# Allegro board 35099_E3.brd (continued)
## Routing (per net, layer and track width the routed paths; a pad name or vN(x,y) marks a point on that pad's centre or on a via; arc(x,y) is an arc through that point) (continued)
N19546803: length 3.1
  TOP w0.114: U108.A2 R249.2
N19546823: length 2.5
  TOP w0.114: U108.A5 79.53,55.32 R250.2
N19546843: length 2
  TOP w0.114: R251.2 U108.B1
N19546881: length 3.4
  TOP w0.114: R247.2 82.53,48.33 82.03,48.82 82.03,50.82 U108.C2
N19798378: length 1.7
  TOP w0.114: J38.6 SH17.1
N19798386: length 1.7
  TOP w0.114: J38.38 SH21.1
N19798394: length 2.1
  TOP w0.114: SH20.1 63.44,105.57 J38.28
N19798402: length 1.7
  TOP w0.114: J38.26 SH19.1
N19798410: length 2
  TOP w0.114: J38.24 63.38,106.84 SH18.1
N19799787: length 2.1
  TOP w0.114: SH11.2 72.51,111.28 J38.9
N19799813: length 1.7
  TOP w0.114: SH12.2 J38.11
N19799835: length 1.7
  TOP w0.114: J38.15 SH13.2
N19799857: length 2.1
  TOP w0.114: SH14.2 72.45,108.74 J38.17
N19830189: length 3.1
  TOP w0.114: R363.2 U19.A2
N19830205: length 2.4
  TOP w0.114: U19.B1 62.54,49.32 R365.1
N19830207: length 1.5
  TOP w0.114: R365.2 TP45.1
N19830220: length 5.1
  TOP w0.114: U19.A3 63.04,51.82 63.54,51.82 64.04,51.32 64.04,48.82 R364.1
N19830414: length 2
  TOP w0.114: R362.2 U19.A5
N19896770: length 3.6
  TOP w0.114: J45.9 61.08,39.33 R201.2
N19896842: length 3.4
  TOP w0.114: J45.11 61.58,39.79 R202.2
N19896868: length 3.2
  TOP w0.114: R203.2 62.08,40.24 J45.13
N19896897: length 3
  TOP w0.114: J45.15 62.58,40.69 R204.2
N19896926: length 2.8
  TOP w0.114: R205.2 63.08,41.13 J45.17
N19896944: length 3
  TOP w0.114: R206.2 63.58,40.68 J45.19
N19896964: length 3.2
  TOP w0.114: J45.21 64.08,40.22 R207.2
N19896972: length 3.4
  TOP w0.114: J45.23 64.58,39.77 R208.2
N19896981: length 93
  TOP w0.114: v1(136.78,28.96) 148.26,28.96 D23.C ; J45.6 60.33,29.46 62.61,27.18 76.96,27.18 v1(77.98,28.19)
  L3_IN1 w0.114: v1(136.78,28.96) 135.71,27.89 86.78,27.89 86.21,28.45 78.23,28.45 v1(77.98,28.19)
N19897044: length 91.4
  TOP w0.114: v1(136.27,23.37) 148.17,23.37 D22.C ; v1(77.09,28.19) 76.45,27.56 64.91,27.56 62.83,29.64 J45.16
  L3_IN1 w0.114: v1(136.27,23.37) 134.62,25.02 80.26,25.02 v1(77.09,28.19)
N19897050: length 1.2
  TOP w0.114: R225.1 D23.A
N19897088: length 2.9
  TOP w0.114: J45.20 v1(63.83,32.44)
  BOTTOM w0.114: R209.2 63.72,32.54 v1(63.83,32.44)
N19897150: length 1.2
  TOP w0.114: D22.A R224.1
N19897259: length 3.1
  TOP w0.114: J45.8 v1(60.83,32.44)
  BOTTOM w0.114: R215.1 60.83,32.54 v1(60.83,32.44)
N19897289: length 2.9
  TOP w0.114: J45.10 v1(61.33,31.93)
  BOTTOM w0.114: v1(61.33,31.93) 61.33,32.99 R216.1
N19897307: length 2.7
  TOP w0.114: J45.12 v1(61.83,32.44)
  BOTTOM w0.114: R217.1 61.81,32.45 v1(61.83,32.44)
N19897327: length 2.9
  TOP w0.114: J45.14 v1(62.33,31.93)
  BOTTOM w0.114: v1(62.33,31.93) 62.33,33.01 R218.1
N19898667: length 1.5
  TOP w0.114: Y8.3 R200.1
N20219970: length 2.2
  TOP w0.114: TP46.1 R393.3
N169660511: length 1.7
  TOP w0.254: C15.2 34.8,102.11 R27.1
N169660621: length 1
  TOP w0.203: C17.2 R38.1

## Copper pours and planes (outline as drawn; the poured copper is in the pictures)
2V5_OUT on TOP: 112.8,74.64 111.8,75.64 111.8,77.42 111.94,77.56 113.11,77.56 113.11,76.2 122.59,76.2 122.97,75.82 122.97,74.75 122.86,74.64
3V3_OUT on TOP: 105.31,35.18 105.31,36.5 108,36.5 110.16,38.66 115.84,38.66 116.09,38.41 116.09,37.43 116,37.34 110.62,37.34 108.46,35.18
3V3_OUT_USB1 on TOP: 102.02,50.37 99.98,48.33 99.98,46.68 101.38,46.68 101.38,47.58 102.67,48.87 103.42,48.87 103.61,49.06 103.61,50.37
+2.5V_LINK on L3_IN1: 111.63,79.38 111.63,86.42 98.55,99.5 98.55,105 100.27,106.72 118.48,106.72 129.98,118.23 132.21,118.23 135.38,115.05 135.38,111.56 133.48,109.66 131.57,109.66 131.57,108.41 133.77,108.41 134.11,108.07 134.11,102.99 130.13,99.01 125.37,99.01 121.73,95.37 121.73,89.65 121.73,89.65 121.73,88.07 112.52,78.86 112.15,78.86
+5V on TOP: 103.44,48.39 102.59,48.39 102.59,47.12 102.06,46.58 102.06,37.99 102.34,37.71 102.34,37.01 103.2,37.01 103.2,37.62 103.34,37.76 105.12,37.76 105.27,37.6 105.27,37.01 106.15,37.01 106.15,38.29 105.77,38.67 104.33,38.67 104.11,38.89 104.11,45.51 105.15,46.55 106.82,46.55 108.58,48.31 108.58,53.34 108.2,53.72 106.55,53.72 105.51,52.68 105.51,49.86 106.48,49.86 106.63,49.71 106.63,48.49 106.5,48.36 105.56,48.36 105.56,47.9 105.27,47.61 103.5,47.61 103.44,47.68
+5V on TOP: 141.74,73.19 144.78,73.19 144.78,77.61 141.88,77.61 141.3,77.04 141.3,73.63
+5V_EXT on TOP: 139.5,65.76 138.51,66.75 138.51,73.86 138.15,74.22 137.19,74.22 136.53,74.88 136.53,77.62 136.58,77.67 136.75,77.67 136.78,77.65 136.78,77.39 136.93,77.25 137.05,77.25 137.13,77.16 137.13,76.83 137.62,76.35 138.66,76.35 140.97,74.04 140.97,68.76 141.53,68.2 146.53,68.2 147.24,67.49 149.11,67.49 149.12,67.48 149.12,67.14 148.18,67.14 147.9,66.87 147.9,66.74 147.9,66.73 147.9,66.38 147.28,65.76
+5V_LINK on TOP: 145.24,74.22 147.75,74.22 148.08,74.55 148.08,75.31 147.83,75.56 145.29,75.56 145.03,75.31 145.03,74.42
+5V_LINK on TOP: 122.96,73.4 118.36,73.4 118.17,73.2 118.17,70.81 118.71,70.27 121.48,70.27 122.96,71.75
+5V_LINK on TOP: 143.66,106.43 141.43,106.43 141.12,106.12 141.12,105.05 141.42,104.76 143.52,104.76 143.81,105.04 143.81,105.04 143.81,106.27
+5V_LINK on L3_IN1: 120.02,70.74 119.25,71.5 119.25,72.14 121.28,74.17 134.8,74.17 141.48,80.85 141.48,105.66 142.11,106.3 143.38,106.3 144.15,105.54 144.15,78.99 148.08,75.06 148.08,74.55 147.7,74.17 139.33,74.17 135.9,70.74
GND on TOP (solid shape): 145.91,109.46 145.91,109.31 145.91,109.28 145.9,109.21 145.83,109.17 145.76,109.14 145.69,109.09 145.59,109 143.43,109 143.43,109.09 143.46,109.11 143.55,109.18 143.59,109.28 143.59,109.84 145.53,109.84
GND on TOP (solid shape): 105.15,113.56 105.19,113.51 105.21,113.47 105.18,113.43 105,113.25 104.93,113 104.93,112.93 104.71,112.71 96.11,112.71 96.02,112.77 96.04,112.88 96.71,113.56
GND on TOP (solid shape): 102.23,70.15 101.79,69.71 101.29,69.71 101.22,69.74 101.19,69.82 101.19,70.03 101.16,70.12 101.07,70.15 101.04,70.15 101.02,70.14 100.94,70.26 100.84,70.35 100.8,70.42 100.83,70.5 101.43,71.1 102.23,71.1
GND on TOP (solid shape): 102.23,68.33 102.23,67.54 98.64,67.54 98.55,67.61 98.57,67.72 98.73,67.88 99.52,67.88 99.69,67.73 99.91,67.68 100.21,67.78 100.38,68.05 100.42,68.11 100.49,68.13 100.56,68.12 100.83,68.2 101.02,68.41 101.04,68.4 101.07,68.4 101.16,68.44 101.19,68.53 101.19,68.74 101.22,68.82 101.29,68.85 101.71,68.85
GND on TOP (solid shape): 33.82,101.35 34.12,101.05 34.23,100.98 34.35,100.95 38.06,100.95 38.15,100.9 38.15,100.81 38.11,100.7 38.1,100.58 38.18,100.31 38.39,100.13 38.38,100.1 38.38,100.08 38.42,99.99 38.51,99.95 38.71,99.95 38.8,99.99 38.84,100.08 38.83,100.1 38.83,100.13 38.92,100.18 38.99,100.25 39.24,100.25 39.32,100.18 39.41,100.13 39.4,100.1 39.4,100.08 39.4,100.05 39.41,100.03 39.19,99.84 39.12,99.57 39.12,99.53 38.92,99.33 37.61,99.33 36.3,100.64 36.19,100.71 36.07,100.74 34.22,100.74 33.65,101.3 33.71,101.35
GND on TOP (solid shape): 112.95,105.96 113.12,105.82 113.33,105.77 113.43,105.77 113.52,105.8 113.61,105.79 113.66,105.71 113.66,104.41 113.38,104.13 113.28,104.14 113.01,104.06 112.83,103.85 112.71,103.84 112.65,103.73 112.65,103.53 112.71,103.42 112.83,103.41 113.01,103.2 113.28,103.12 113.38,103.13 113.56,102.95 113.51,102.9 112.06,102.9 111.95,102.87 111.86,102.81 109.19,100.15 109.08,100.13 109.02,100.22 109.02,100.97 111.38,103.33 111.44,103.42 111.46,103.53 111.46,105.42 112.01,105.96
GND on TOP (solid shape): 47.18,82.5 47.24,82.5 48.17,82.5 48.32,82.39 48.5,82.34 48.52,82.34 48.59,82.27 48.59,82.26 48.68,82.01 48.89,81.85 48.92,81.84 48.92,79.42 48.34,78.84 48.11,78.84 48.01,78.92 47.9,78.97 47.83,79.05 47.86,79.14 47.91,79.21 47.96,79.28 47.98,79.28 48.01,79.27 48.1,79.31 48.13,79.4 48.13,79.6 48.1,79.69 48.02,79.73 47.98,79.74 47.98,80.35 47.84,80.69 47.5,80.84 47.27,80.78 47.1,80.62 47.06,80.6 47.02,80.61 46.98,80.65 46.98,81.22 46.99,81.23 47.01,81.29 47.02,81.34 47.02,82.26 47.01,82.31 46.99,82.36 46.99,82.47 47.07,82.52 47.11,82.52
GND on TOP (solid shape): 116.3,105.57 116.32,105.47 116.24,105.4 116.02,105.31 115.87,105.12 115.85,105.13 115.82,105.13 115.73,105.09 115.7,105 115.7,104.8 115.7,104.77 115.68,104.69 115.61,104.65 115.28,104.5 115.15,104.17 115.18,103.99 115.28,103.84 115.28,103.83 115.3,103.69 115.38,103.58 115.42,103.53 115.43,103.48 115.39,103.45 114.95,103.45 114.87,103.43 114.81,103.39 113.93,103.39 113.78,103.54 113.78,103.73 114.15,104.09 114.21,104.18 114.23,104.29 114.23,106.44 114.28,106.53 114.37,106.54 114.46,106.51 114.55,106.5 114.77,106.55 114.94,106.7 115.17,106.7
GND on TOP (solid shape): 50.59,98.21 50.67,98.17 50.69,98.08 50.69,98.06 50.69,97.85 50.73,97.76 50.82,97.73 50.84,97.73 50.87,97.74 50.9,97.67 50.95,97.61 50.97,97.55 50.95,97.48 50.9,97.42 50.87,97.36 50.84,97.36 50.82,97.37 50.73,97.33 50.69,97.24 50.69,97.04 50.73,96.95 50.82,96.91 50.84,96.91 50.87,96.92 50.91,96.85 50.96,96.78 50.97,96.77 50.97,96.72 50.96,96.7 50.88,96.56 50.85,96.39 50.86,96.31 50.88,96.23 50.87,96.14 50.78,96.1 49.72,96.1 49.58,96.24 49.58,96.52 49.74,96.7 49.8,96.94 49.72,97.21 49.51,97.4 49.52,97.42 49.52,97.45 49.52,97.47 49.51,97.5 49.72,97.68 49.8,97.95 49.79,98.05 49.95,98.21
GND on TOP (solid shape): 51.87,73.98 51.98,74.01 52.05,73.91 52.05,73.52 52,73.4 51.98,73.28 52.06,73.01 52.28,72.83 52.34,72.76 52.31,72.67 51.6,71.96 51.54,71.86 51.51,71.75 51.45,71.68 51.42,71.59 51.42,70.78 51.48,70.64 51.61,70.59 52.02,70.59 52.08,70.6 52.14,70.63 52.2,70.6 52.26,70.59 52.36,70.59 52.45,70.53 52.44,70.43 52.38,70.29 52.35,70.14 52.39,69.96 52.5,69.8 52.53,69.69 52.43,69.62 52.26,69.62 52.2,69.61 52.15,69.59 52.08,69.57 52.02,69.6 51,70.61 51,73.51 51.37,73.51 51.5,73.56 51.56,73.7 51.56,73.77 51.57,73.8 51.61,73.82 51.71,73.84 51.79,73.9
GND on TOP (solid shape): 52.11,68.36 52.11,68.05 52.02,67.93 51.97,67.78 51.95,67.74 51.91,67.74 51.85,67.74 51.37,67.26 51.85,66.77 52.07,66.82 52.24,66.96 52.28,67 52.34,67.06 52.58,67.06 52.66,67.03 52.69,66.96 52.69,65.79 50.55,63.65 49.98,63.65 49.9,63.69 49.89,63.78 49.91,63.86 49.92,63.95 49.88,64.13 49.78,64.28 49.77,64.32 49.78,64.35 49.89,64.51 49.92,64.69 49.78,65.04 49.44,65.18 49.23,65.13 49.07,65 47.43,65 47.14,65.29 47.12,65.41 47.21,65.47 48.97,65.47 49.09,65.49 49.19,65.56 52.02,68.39 52.02,68.39
GND on TOP (solid shape): 140.23,17.06 140.31,17.03 140.33,16.95 140.33,16.9 140.35,16.75 140.42,16.62 140.43,16.51 140.34,16.46 140.3,16.46 140.17,16.4 140.11,16.27 140.11,14.74 140.14,14.64 140.22,14.57 140.25,14.56 140.25,13.72 140.27,13.61 140.33,13.52 140.98,12.87 141,12.76 140.91,12.7 140.62,12.7 140.51,12.67 140.41,12.61 139.67,11.87 139.6,11.77 139.58,11.65 139.58,10.53 139.55,10.51 139.49,10.44 139.46,10.35 139.46,8.83 139.52,8.69 139.65,8.64 140.11,8.64 140.16,8.64 140.21,8.66 140.25,8.64 140.3,8.64 140.76,8.64 140.77,8.64 140.85,8.61 140.88,8.53 140.88,7.19 139.98,6.28 139.86,6.32 139.79,6.41 139.84,6.51 140.02,6.69 140.09,6.93 139.95,7.27 139.61,7.41 139.54,7.41 139.26,7.68 139.26,17.06
GND on TOP (solid shape): 97.37,75.55 97.53,75.45 97.59,75.39 97.58,75.31 97.56,75.26 97.55,75.21 97.55,74.02 97.61,73.88 97.74,73.82 98.92,73.82 99.36,73.38 99.36,72.52 99.05,72.2 98.95,72.21 98.68,72.13 98.49,71.92 98.37,71.91 98.32,71.81 98.32,71.6 98.37,71.5 98.49,71.49 98.57,71.37 98.66,71.28 98.66,70.97 98.61,70.91 96.85,70.91 96.74,70.89 96.65,70.83 96.24,70.42 96.15,70.39 96.07,70.46 96.05,70.5 96.02,70.55 96.02,71.28 96.12,71.37 96.19,71.49 96.31,71.5 96.37,71.6 96.37,71.81 96.31,71.91 96.19,71.92 96.13,72.03 96.04,72.11 96.02,72.12 96.02,72.22 96.94,72.22 97.07,72.28 97.13,72.42 97.13,73.61 97.07,73.74 96.94,73.8 95.86,73.8 95.4,74.26 95.4,75.17 95.86,75.63 96.29,75.63 96.47,75.47 96.71,75.41 96.98,75.49 97.16,75.7 97.19,75.69 97.21,75.69 97.24,75.69 97.26,75.7
GND on TOP (solid shape): 117.82,108.97 117.86,108.97 118.33,108.97 118.34,108.93 118.37,108.85 118.42,108.79 119.68,107.53 119.77,107.46 119.88,107.44 121.52,107.44 121.61,107.38 121.6,107.27 121.55,107.21 121.51,107.15 121.49,107.15 121.46,107.16 121.37,107.12 121.34,107.03 121.34,106.83 121.37,106.74 121.46,106.7 121.49,106.7 121.51,106.71 121.7,106.5 121.97,106.42 122.21,106.48 122.39,106.64 125.75,106.64 125.78,106.61 125.83,106.53 125.78,106.45 125.67,106.31 125.62,106.13 125.65,105.98 125.73,105.86 125.73,105.13 125.53,104.93 125.47,104.83 125.44,104.72 125.44,103.54 125.28,103.36 125.22,103.12 125.3,102.85 125.51,102.67 125.5,102.64 125.5,102.62 125.5,102.59 125.51,102.57 125.4,102.49 125.31,102.39 124.05,102.39 120.71,105.73 120.61,105.8 120.5,105.82 118.31,105.82 116.61,107.52 116.59,107.61 116.66,107.69 116.92,107.86 117.02,108.15 117.01,108.23 117.68,108.89 117.71,108.92 117.73,108.95 117.75,108.97 117.78,108.98
GND on TOP (solid shape): 97.41,86.14 97.05,85.77 96.92,85.27 97.12,84.66 97.65,84.3 97.65,83.66 97.57,83.6 97.51,83.53 96.83,83.53 96.65,83.69 96.41,83.75 96.14,83.67 95.95,83.46 95.93,83.47 95.9,83.47 95.88,83.47 95.85,83.46 95.78,83.57 95.68,83.66 95.68,84.3 96.21,84.66 96.41,85.27 95.39,86.29 94.38,85.27 94.58,84.66 95.11,84.3 95.11,83.66 94.94,83.48 94.89,83.24 94.89,83.2 94.84,83.15 94.78,83.21 94.69,83.27 94.58,83.29 89.37,83.29 86.35,86.31 86.25,86.38 86.14,86.4 76.78,86.4 76.7,86.43 76.68,86.52 76.68,86.56 76.68,86.6 76.68,86.68 76.66,86.76 76.67,86.85 76.75,86.89 97.41,86.89
GND on TOP (solid shape): 116.1,86.23 116.23,86.14 116.39,86.11 117.64,86.11 117.69,86.06 117.69,85.69 117.65,85.61 117.55,85.6 117.52,85.61 117.48,85.61 116.72,85.61 116.64,85.59 116.57,85.53 116.55,85.51 116.07,85.51 115.96,85.49 115.87,85.43 114.03,83.6 112.79,83.6 112.42,84.13 111.81,84.33 111.3,84.19 110.92,83.8 110.91,83.78 110.83,83.78 110.83,83.94 111.02,84.33 110.83,84.72 110.83,85.17 110.9,85.26 111.01,85.23 111.36,84.94 111.81,84.84 112.42,85.04 112.79,85.57 113.44,85.57 113.62,85.42 113.84,85.37 114.2,85.52 114.35,85.88 114.31,86.07 114.2,86.24 114.18,86.35 114.27,86.41 114.55,86.41 114.6,86.4 114.66,86.4 115.17,86.4 115.18,86.35 115.22,86.28 115.3,86.25 115.51,86.25 115.6,86.28 115.63,86.37 115.63,86.4 115.62,86.42 115.69,86.46 115.87,86.46
GND on TOP (solid shape): 124.11,111.93 124.21,111.86 124.18,111.75 124.07,111.62 124.01,111.46 123.95,111.39 123.86,111.39 123.74,111.44 123.62,111.46 123.28,111.31 123.14,110.97 123.15,110.88 123.18,110.79 123.17,110.69 123.08,110.65 122.93,110.65 122.42,111.16 122.43,111.25 122.28,111.61 121.92,111.76 121.65,111.68 121.46,111.47 121.44,111.48 121.41,111.48 121.32,111.44 121.28,111.35 121.28,111.15 121.32,111.06 121.41,111.02 121.44,111.03 121.46,111.03 121.65,110.82 121.92,110.74 122.01,110.75 122.41,110.36 122.42,110.3 122.38,110.27 122.34,110.27 122.33,110.29 122.15,110.44 121.92,110.49 121.65,110.41 121.46,110.2 121.44,110.21 121.41,110.21 121.32,110.17 121.28,110.08 121.28,109.88 121.32,109.79 121.41,109.75 121.44,109.76 121.46,109.76 121.49,109.71 121.52,109.67 121.53,109.61 121.48,109.58 120.54,109.58 120.2,109.92 120.2,111.07 120.18,111.18 120.12,111.28 119.73,111.66 119.64,111.72 119.53,111.74 118.03,111.74 117.94,111.8 117.96,111.91 117.97,111.93
GND on TOP (solid shape): 94.76,57.81 94.82,57.9 94.93,57.88 95.24,57.57 95.24,55.96 95.1,55.79 95.04,55.57 95.19,55.23 95.53,55.08 95.58,55.09 95.63,55.1 95.71,55.07 95.75,55 95.75,52.19 95.77,52.08 95.83,51.99 97.13,50.69 97.13,50.61 97.27,50.27 97.61,50.13 97.61,50.13 97.71,50.07 97.69,49.96 97.27,49.54 96.88,49.54 96.71,49.68 96.49,49.73 96.15,49.59 96.01,49.25 96.06,49.05 96.18,48.88 96.21,48.77 96.12,48.7 95.35,48.7 93.65,50.41 93.62,50.48 93.66,50.56 93.78,50.72 93.83,50.93 93.78,51.14 93.63,51.32 93.63,51.81 93.68,51.89 93.77,51.9 93.86,51.88 93.95,51.87 94.29,52.01 94.44,52.35 94.41,52.52 94.32,52.67 94.32,53.85 94.35,53.92 94.43,53.95 94.47,53.95 94.81,54.09 94.95,54.43 94.9,54.65 94.76,54.82
GND on TOP (solid shape): outline of 189 points within 114.75,61.56 142.76,85.69
GND on TOP (solid shape): outline of 101 points within 115.95,100.7 120.01,104.89
GND on TOP (solid shape): outline of 100 points within 31.2,86.49 38.48,94.93
GND on TOP (solid shape): 47.18,94.09 47.29,94.11 47.36,94.02 47.36,92.87 47.38,92.76 47.44,92.67 47.89,92.22 47.88,92.19 47.83,92.03 47.82,91.87 47.93,91.46 48.23,91.15 48.28,91.09 48.26,91 48.19,90.86 48.16,90.7 48.21,90.48 48.36,90.31 48.39,90.2 48.3,90.13 46.57,90.13 46.49,90.17 46.47,90.25 46.48,90.3 46.48,90.35 46.42,90.59 46.26,90.77 46.26,90.94 46.42,91.13 46.48,91.36 46.33,91.72 45.97,91.87 45.7,91.79 45.52,91.58 45.47,91.59 45.42,91.58 45.23,91.79 44.96,91.87 44.76,91.83 44.59,91.71 44.57,91.69 44.49,91.69 44.23,91.95 44.2,92.05 44.27,92.12 44.41,92.2 44.52,92.32 44.59,92.36 44.67,92.34 44.8,92.28 44.96,92.25 45.23,92.33 45.42,92.54 45.47,92.53 45.52,92.54 45.7,92.33 45.97,92.25 46.31,92.38 46.48,92.71 46.48,92.72 46.57,92.81 46.64,92.81 46.99,92.95 47.13,93.29 47.08,93.51 46.93,93.68 46.89,93.75 46.92,93.83
GND on TOP (solid shape): 134.47,75.35 134.58,75.37 134.64,75.28 134.64,74.08 134.53,74.08 134.4,74.02 134.34,73.89 134.34,73 134.4,72.86 134.53,72.81 135.32,72.81 135.45,72.86 135.51,73 135.51,73.15 137.43,73.15 137.45,73.11 137.49,73.07 137.51,72.96 137.41,72.9 137.01,72.9 136.87,72.97 136.72,73 136.37,72.86 136.23,72.52 136.27,72.33 136.37,72.18 136.48,72.07 136.63,71.97 136.82,71.93 137.69,71.93 137.77,71.91 137.85,71.91 138.01,71.93 138.15,72.01 138.26,72.02 138.32,71.93 138.32,67.09 138.28,67.04 138.23,67.05 138.18,67.11 138.08,67.17 137.96,67.2 134.27,67.2 134.17,67.26 134.2,67.37 134.55,67.72 134.62,67.72 134.96,68.54 134.14,68.2 134.14,68.13 133.66,67.65 127.89,67.65 127.8,67.69 127.8,67.79 127.84,67.9 127.85,68.01 127.84,68.08 130.92,71.15 133.4,71.15 133.4,70.99 133.46,70.86 133.59,70.8 134.38,70.8 134.51,70.86 134.57,70.99 134.57,71.88 134.51,72.02 134.38,72.07 133.59,72.07 133.46,72.02 133.4,71.88 133.4,71.72 131.08,71.72 130.99,71.79 131.01,71.9
GND on TOP (solid shape): outline of 87 points within 110.83,86.14 117.38,90.81
GND on TOP (solid shape): 131.22,109.14 131.3,109.1 131.38,109.02 131.47,108.96 131.48,108.96 131.76,108.68 131.86,108.61 131.98,108.57 132.01,108.56 132.02,108.52 132.09,108.3 132.27,108.16 132.28,108.16 132.56,107.88 132.66,107.81 132.78,107.77 132.81,107.76 132.82,107.72 132.87,107.55 132.98,107.41 133.03,107.33 132.98,107.25 132.94,107.21 132.9,107.16 132.82,107.12 132.42,107.32 132.02,107.12 131.93,107.16 131.89,107.21 131.85,107.25 131.81,107.33 131.85,107.41 131.97,107.55 132.01,107.73 131.89,108.01 131.62,108.12 131.44,108.08 131.3,107.96 131.22,107.92 130.82,108.12 130.42,107.92 130.02,108.12 129.62,107.92 129.53,107.96 129.49,108.01 129.45,108.05 129.41,108.13 129.61,108.53 129.41,108.93 129.45,109.01 129.49,109.05 129.53,109.1 129.62,109.14 129.7,109.1 129.84,108.98 130.02,108.93 130.1,108.94 130.18,108.97 130.65,108.97 130.74,108.94 130.82,108.93 130.99,108.98 131.13,109.1
GND on TOP (solid shape): outline of 92 points within 102.51,90.19 108.69,94.92
GND on TOP (solid shape): outline of 233 points within 101.68,95.9 107.84,99.08
GND on TOP (solid shape): outline of 85 points within 82.32,47.94 87.28,52.07
GND on TOP (solid shape): outline of 265 points within 66.2,63.83 72.33,84.78
GND on TOP (solid shape): outline of 121 points within 43.46,65.57 51.12,69.34
GND on TOP (solid shape): outline of 451 points within 139.86,53.66 151.76,84.67
GND on TOP (solid shape): outline of 190 points within 91.68,62.26 96.28,67.75
GND on TOP (solid shape): outline of 496 points within 69.27,66.62 87.46,74.38
GND on TOP (solid shape): outline of 498 points within 48.39,90.71 70.55,101.27
GND on TOP (solid shape): outline of 463 points within 59.06,27.85 75.85,34.86
GND on TOP (solid shape): outline of 213 points within 97.19,101.23 115.84,114.25
GND on TOP (solid shape): outline of 707 points within 48.7,60.3 69.31,90.96
GND on TOP (solid shape): outline of 958 points within 68.36,73.26 94.86,88.14
GND on TOP (solid shape): outline of 412 points within 43.45,65.3 60.32,86.14
GND on TOP (solid shape): outline of 475 points within 61.83,44.48 89.19,61.81
GND on TOP (solid shape): outline of 1564 points within 51.95,90.96 75.5,121.28
GND on TOP (solid shape): outline of 1829 points within 73.57,89.67 107.19,108.05
GND on TOP (solid shape): outline of 3458 points within 56.93,94.07 123.86,121.28
GND on TOP (solid shape): outline of 7156 points within 88.61,62.17 151.76,121.28
GND on TOP (solid shape): outline of 25398 points within 0.64,0.64 151.76,121.28
GND on TOP: 89.98,68.54 89.98,61.79 97.21,61.79 97.21,68.54
GND on BOTTOM, L2_GND: 151.76,0.64 0.64,0.64 0.64,121.28 151.76,121.28
GND on L5_PWR: 0.55,121.3 151.52,121.3 151.52,0.83 0.55,0.83
P1V8_CODEC on TOP: 35.41,90.75 31.88,90.75 31.53,90.41 31.53,88.68 31.67,88.54 35.06,88.54 35.56,89.04 35.56,90.6
P1V8_CODEC on L3_IN1: 33.29,90.73 45.23,102.67 46.5,102.67 46.75,102.42 46.75,98.35 36.47,88.07 32.15,88.07 31.51,88.7 31.51,90.35 31.89,90.73
VBST/VDDP_1 on TOP: 43.21,76.92 43.01,76.73 40.98,76.73 40.68,77.04 40.68,81.66 40.83,81.81 41.34,81.81 41.69,81.46 41.69,80.59 42.49,79.79 42.49,79.79 43.26,79.02 43.26,78.18 43.15,78.07 43.1,78.07 42.96,78.22 41.66,78.22 41.53,78.09 41.53,77.44 41.64,77.33 42.7,77.33 42.77,77.41 43.02,77.41 43.1,77.48 43.57,77.48 43.62,77.42 43.62,77.32 43.59,77.28 43.29,77.28 43.21,77.2
VBST/VDDP_2 on TOP: 43.62,66.55 43.07,66.55 42.89,66.37 41.54,66.37 41.33,66.59 41.33,67.17 41.45,67.3 42.76,67.3 42.9,67.16 43.17,67.16 43.23,67.22 43.23,68.06 43.12,68.17 42.53,68.17 41.59,69.1 41.59,71.26 41.21,71.64 40.73,71.64 40.51,71.42 40.51,66.08 40.65,65.94 43.18,65.94 43.26,66.01 43.26,66.27 43.32,66.33 43.6,66.33 43.62,66.36
VDD_AMP on TOP: 45.09,77.09 45.2,77.09 45.25,77.04 45.25,76.66 45.87,76.04 45.87,74.41 45.49,74.03 41.16,74.03 41.14,74.05 41.14,74.85 41.24,74.96 44.89,74.96 44.89,76.23 45.02,76.35 45.02,77.03
VDD_AMP on TOP: 41.95,86.56 39.66,86.56 39.5,86.4 39.5,84.53 39.59,84.44 42.77,84.44 42.88,84.54 42.88,85.64
VDD_AMP on TOP: 44.62,64 44.62,64.94 45.02,65.34 45.02,66.15 45.05,66.18 45.21,66.18 45.26,66.13 45.26,65.8 45.48,65.58 45.48,64
VDD_AMP on L3_IN1: 27.17,61.33 23.77,61.33 23.01,62.09 23.01,63.27 38.38,78.64 38.38,84.9 40.03,86.55 42.05,86.55 43.33,85.27 43.33,76.71 43.98,76.06 45.11,76.06 45.74,75.43 45.74,74.16 45.24,73.66 39.5,73.66
VDD_CODEC on TOP: 36.39,97.92 36.39,99.35 36.07,99.67 33.97,99.67 33.91,99.61 33.91,97.97 34,97.88 36.35,97.88
VDD_CODEC on L3_IN1: 45.39,102.92 44.72,102.92 39.59,97.79 34.06,97.79 33.87,97.98 33.87,99.57 41.16,106.86 48.78,106.86 50.69,104.96 55.9,104.96 59.45,101.4 59.45,99.01 49.31,99.01
VDD_JACK on TOP: 24.18,65.89 13.56,65.89 12.37,64.69 12.37,62.13 13.36,61.14 20.6,61.14 23.42,63.96 24.49,63.96 24.79,64.26 24.79,65.28
VDD_LDO_3V3 on L4_IN2: 100.31,43.94 88.01,56.24 88.01,74.65 88.3,74.93 88.3,91.58 89.46,92.74 90.47,92.74 91.74,91.47 91.74,73.93 90.41,72.6 90.41,61.84 101.62,50.63 101.62,44.57 101,43.94
VDD_LINK on BOTTOM: 111.35,120.6 103.96,120.6 96.19,112.83 91.16,112.83 88.87,110.54 88.87,109.17 90.22,107.82 99.75,107.82 100.66,108.74 101.07,108.74 101.73,108.08 101.73,90.98 102.95,89.76 103.5,89.76 107.75,94.01 107.75,96.6 107.29,97.05 107.29,100.89 109.52,103.12 109.52,110.29 112.29,113.06 112.29,119.66
VDD_MEM on L3_IN1: 57.4,51.82 57.4,50.95 67.46,40.89 68.96,40.89 69.22,41.15 69.22,48.39 70.1,49.28 83.82,49.28 85.62,51.08 85.62,53.57 83.69,55.5 61.09,55.5
VDDCORE on L4_IN2: 96.22,61.52 96.22,68.19 101.25,73.22 101.25,74.75 100.87,75.13 98.08,75.13 90.72,67.77 90.72,61.52
VDDE_A on L3_IN1: 44.85,66.54 51.71,66.54 52.73,67.56 52.73,75.68 57.17,80.13 57.26,80.13 57.26,80.93 56.41,81.78 50.95,81.78 49.43,83.3 48.66,83.3 44.98,79.62 44.98,74.92 43.84,73.78 43.84,67.56
VDDIO1 on L3_IN1: 93.09,78.61 93.09,74.04 103.63,74.04 104.78,75.18 104.78,77.09 99.44,82.42 96.9,82.42
VDDIO1 on L5_PWR: 55.71,113.3 51.09,108.68 51.09,96.74 57.4,90.42 57.4,77.47 59.69,75.18 76.8,75.18 79.41,77.8 87.79,77.8 91.98,73.61 94.02,73.61 96.56,76.15 100.87,76.15 101.38,76.65 101.38,79.83 99.76,81.45 99.76,98.17 92.96,104.97 92.96,110.11 92.2,110.87 58.42,110.87 55.99,113.3
(no net) on TOP: 151.76,0.64 0.64,0.64 0.64,121.28 151.76,121.28
INB_1 on TOP: 43.43,78.15 43.43,79.36 40.93,81.86 40.93,83.89 42.71,83.89 42.71,83 43.64,82.07 43.64,78.15
INB_2 on TOP: 42.51,73.24 44.2,73.24 44.32,73.11 44.32,69.22 43.64,68.53 43.64,67.23 43.43,67.23 43.43,68.21 43.24,68.4 42.81,68.4 42.24,68.97 42.2,68.97 41.91,69.27 41.91,72.64
LDO2_OUT on TOP: 123.73,54.94 123.73,52.27 122.59,52.27 122.59,54.94
LX1 on TOP: 119.03,50.67 121.83,50.67 121.83,49.98 120.36,48.51 119.03,48.51
LX2 on TOP: 119.92,46.94 119.92,48.33 121.45,49.86 122.34,49.86 122.34,46.94
SW1_OUT on TOP: 118.11,46.86 118.11,51.05 114.72,51.05 114.72,46.86
SW2_OUT on TOP: 120.05,49.85 124.71,49.85 124.71,44.58 121.79,41.66 120.05,41.66
SW2_OUT_MCU on L3_IN1: 104.81,58.49 101.12,58.49 96.82,62.81 91.48,62.81 91.22,63.06 91.22,65.99 91.86,66.62 98.59,66.62 104.81,60.4
USB_HS_HOST_VBUS on TOP: 143.59,85.21 148.62,85.21 148.62,84.91 148.56,84.86 147.48,84.86 147.47,84.85 147.47,82.18 146.39,81.1 145.52,81.1 141.34,76.92 137.36,76.92 137.33,76.95 137.33,77.25 137.13,77.44 137.01,77.44 136.93,77.52 136.93,77.62 136.98,77.67 137.85,77.67 138.51,78.33 138.51,78.71 138.81,79.02 141.38,79.02 141.68,79.32 141.68,83.3
USB_HS_VBUS_TRGT on TOP: 146.63,78.05 146.63,79.93 146.3,80.26 145.16,80.26 145.03,80.14 145.03,77.34 145.92,77.34
USB_VBUS_LINK on TOP: 140.49,106.53 138.2,106.53 137.92,106.25 137.92,105.16 138,105.08 140.61,105.08 140.74,105.21 140.74,106.27
USB_VBUS_LINK on L3_IN1: 131.57,109.47 131.57,108.76 131.7,108.64 134.39,108.64 137.95,105.08 140.54,105.08 140.82,105.36 140.82,106.1 140.41,106.5 138.58,106.5 135.59,109.5 131.6,109.5
N17855945 on TOP: 43.59,77.08 43.51,77.08 43.43,77 43.43,76.9 42.95,76.42 42.75,76.42 42.43,76.1 42.43,75.87 42.65,75.65 43.02,75.65 43.64,76.27 43.64,77.03
N17886097 on TOP: 43.48,66.17 43.61,66.17 43.69,66.09 43.69,65.2 43,64.52 42.67,64.52 42.1,65.09 42.8,65.79 43.26,65.79 43.41,65.94 43.41,66.09
N19515068 on TOP: 142.57,68.45 142.57,70.94 145.16,73.53 145.54,73.53 145.54,70.74 143.26,68.45
N19515078 on TOP: 144.37,105.31 145.31,105.31 147.32,107.31 147.32,107.82 144.63,107.82 144.37,107.57

Small or netless copper shapes (teardrops, artwork), in the pictures only: 12 on TOP

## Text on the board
BOTTOM: 170-35099 REV E2
Ref Des/Silkscreen Bottom: 170-35099 REV E3
User.Comments: CR_SW_1 | CR_PS2_1
Ref Des/Silkscreen Top: 1V8 | 3V3 | JTAG | DMIC | I3C0 | FC0 UART | MIMXRT685-EVK
FABRICATION_NOTES: LAYERS | L1_PS | L3_IN1 | L4_IN2 | L6_SS | TRACE WIDTH | 4.50 | SE | IMPEDANCE | 50.00 | TRACE SPACING | 5.00 | 90.00 | 4.00 | DIFF | 7.00 | 100.00 | REFERENCE LAYER | 2,5 | 2 | 5 | 23. RESISTORS MUST BE POPULATED PIN 1 TO PIN 2 | 22. INTENTIONAL 28 SHORTS AT: | Location           RefDes      Net 1                     Net 2 | (1780.00 4010.76)  JS2       P1V8_CODEC             &  SW2_OUT | (1907.50 4010.00)  JS3       VDD_CODEC              &  SW2_OUT | (2209.50 3040.00)  JS9       VDD_PMOD               &  VDDIO1 | (2209.50 3188.50)  JS7       VDDE_A                 &  VDDIO1 | (2435.00 4031.26)  SH21      N19798386              &  P0_22 | (2435.00 4125.00)  SH20      N19798394              &  P0_23_I2S_DATA_TX | (2435.00 4235.00)  SH18      N19798410              &  P0_25 | (2435.00 4181.26)  SH19      N19798402              &  P0_24 | (2434.68 4431.26)  SH17      N19798378              &  P0_21 | (2702.88 1639.56)  JS12      VDD_MEM                &  SW2_OUT | (2915.00 4250.00)  SH14      P2_26_SWDIO            &  N19799857 | (2915.00 4356.26)  SH12      IF_TDO_SWO             &  N19799813 | (2915.00 4305.00)  SH13      IF_TCK_SWCLK           &  N19799835 | (2915.00 4410.00)  SH11      IF_RST                 &  N19799787 | (3438.82 3945.00)  SH3       N18526135              &  P0_18_FC2_SCL | (3438.54 4088.00)  SH2       N18526137              &  P0_17_FC2_SDA | (3751.00 4619.00)  JS1       GND                    &  IF_DETECT | (3974.78 1765.50)  JS16      VDD_LDO_3V3            &  3V3_OUT_USB1 | (4331.50 3028.60)  SH4       VDD_LDO_3V3            &  USB1_VDD3V3 | (4427.00 3027.00)  JS8       2V5_OUT                &  +2.5V_LINK | (4645.00 1491.65)  JS14      USDHC_SPWR             &  3V3_OUT | (4614.00 2310.00)  JS11      LDO2_OUT               &  VDD_TARGET | (4980.00 3840.00)  JS5       I2PIO2_0-SD0_D(0)_SDA  &  P0_16_FC2_SDA | (5140.00 3840.00)  JS6       I2PIO2_0-SD0_D(0)_SCL  &  P0_15_FC2_SCL | (5606.38 837.87)   JS15      DCDC_3V3               &  VDD_LDO_3V3 | (5596.38 1232.87)  JS17      N18503998              &  NRESET_POR | (5570.00 2810.00)  JS10      5V_SYS                 &  +5V | (5710.88 1454.68)  JS13      V_LED                  &  VDD_TARGET | REF_DES | R132, R300-307, R377-380, R384-398 | 19 | 8 | 16 | DETAIL B | IMPEDANCE REQUIREMENTS | IMPEDANCE TOLERANCE IS 10% | TOLERANCE IS +/- 10%
XSECTION_CHART: *  SURFACE - AIR 0 MIL | *  DIELECTRIC - LPI 0.4 MIL | L1 TOP CONDUCTOR - 1OZ_COPPER 1.7 MIL | *  DIELECTRIC - FR408 2.7 MIL | L2 L2_GND PLANE - 1OZ_COPPER 1.2 MIL | *  DIELECTRIC - FR408 4 MIL | L3 L3_IN1 CONDUCTOR - COPPER 1.2 MIL | *  DIELECTRIC - FR408 40 MIL | L4 L4_IN2 CONDUCTOR - COPPER 1.2 MIL | L5 L5_PWR PLANE - COPPER 1.2 MIL | L6 BOTTOM CONDUCTOR - 1OZ_COPPER 1.7 MIL | DESIGN CROSS SECTION CHART | ___________________________ | TOTAL THICKNESS 62.4 MIL | 1-6
DIMENSION: GRID ORIGIN | PRIMARY DATUM
User.12: 22. THIS FAB_VIAFILL.ART SHOWS LOCATIONS OF VIA-IN-PAD TO BE FILLED. | 1/1 | 2
User.13: [MM] | TEST | MIGUEL C. | E2 | E3 | E1 | D | E | JP21, R146 and R147 added | SCHEMATIC CHANGES | DNP CHANGE AND BOARD NAME CHANGE | SOLDERMASK OPENING TO U12.13.17 | REV CHANGE - SOLDERMASK FOR E1 BUILD | 01-08-20 | 07/01/19 | 10/11/19 | 12/19/19 | 01/06/20 | 01/08/20 | 1      1 | A.Q. | R.B. | C.L.
User.15: FIGURE | FINISHED_SIZE | 6.0 | 8.0 | 35.0 | 36.0 | 40.0 | 41.0 | 51.0 | 63.0 | 166.0 | 15.0 | 31.0 | 43.0 | 59.0 | 67.0 | 94.0 | 125.0 | 34.0x26.0 | 47.0x22.0 | 55.0x33.0 | 59.0x33.0 | DRILL CHART: TOP to BOTTOM | ALL UNITS ARE IN MILS | TOLERANCE_DRILL | +0.0/-6.0 | +0.0/-8.0 | +2.0/-2.0 | +3.0/-3.0 | PLATED | NON-PLATED | QTY | 66 | 1316 | 5 | 2 | 193 | 6 | 4 | 3 | 1
